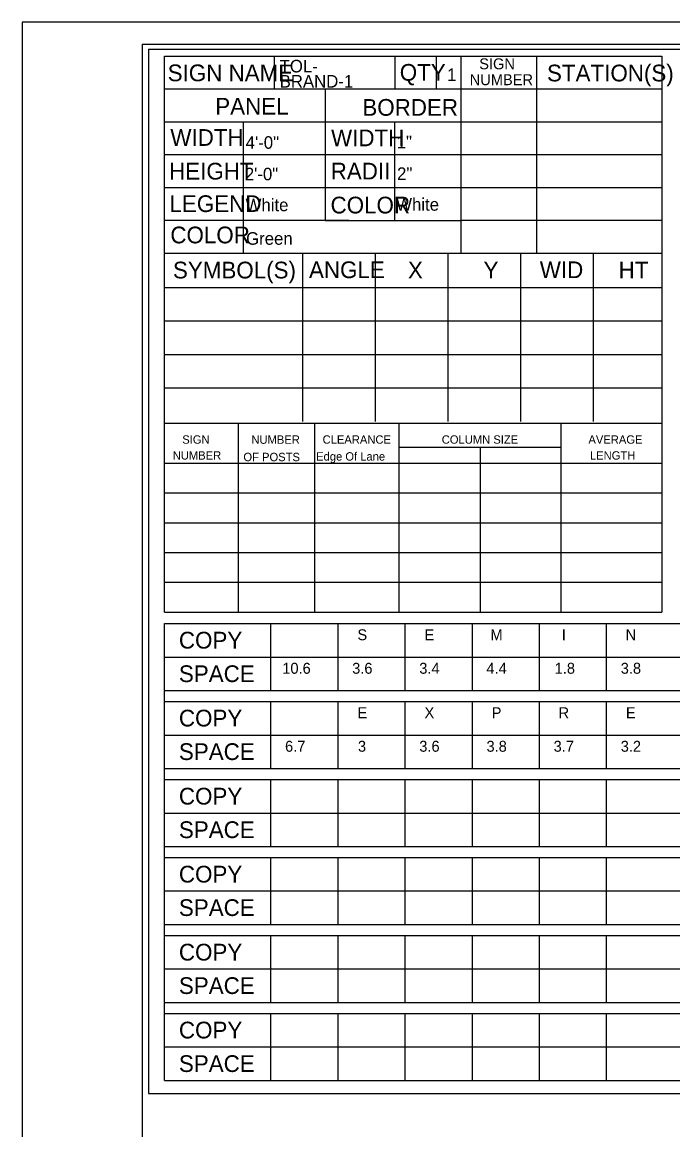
# Model space of a CAD drawing. Extents: x 17890587 to 17890754, y 17897693 to 17897992.
# Drawn here: x 17890586.76 to 17890595.51, y 17897889.3 to 17897904.2 of the extents above; entities that cross this region are included whole.
import ezdxf

# ---------------------------------------------------------------- set-up
doc = ezdxf.new("R2010")
doc.units = 0
for name, color, linetype in [('GSSign', 7, 'Continuous'), ('PlotBorder_dp', 7, 'Continuous'), ('SheetBorder_dp', 7, 'Continuous'), ('SheetLinesMisc2_dp', 7, 'Continuous'), ('TextMinor', 7, 'Continuous')]:
    doc.layers.add(name, color=color, linetype=linetype)

msp = doc.modelspace()

# ---------------------------------------------------------------- linework, layer by layer
at = {"layer": 'PlotBorder_dp'}
msp.add_lwpolyline([(17890586.756, 17897873.104), (17890635.165, 17897873.104), (17890635.165, 17897904.203), (17890586.756, 17897904.203)], close=True, dxfattribs=at)
at = {"layer": 'SheetBorder_dp'}
for q in [(17890588.37, 17897873.397), (17890633.551, 17897903.909)]:
    msp.add_line((17890588.37, 17897903.909), q, dxfattribs=at)
at = {"layer": 'SheetLinesMisc2_dp'}
for p, q in [((17890588.454, 17897903.839), (17890611.019, 17897903.839)), ((17890588.454, 17897903.839), (17890588.454, 17897889.792)), ((17890588.67, 17897896.269), (17890588.67, 17897903.746)), ((17890588.67, 17897903.746), (17890595.362, 17897903.746)), ((17890590.145, 17897903.746), (17890590.145, 17897903.304)), ((17890591.772, 17897903.746), (17890591.772, 17897903.304)), ((17890592.328, 17897903.746), (17890592.328, 17897903.304)), ((17890592.659, 17897903.746), (17890592.659, 17897901.096)), ((17890593.677, 17897903.746), (17890593.677, 17897901.096)), ((17890595.362, 17897903.746), (17890595.362, 17897896.269)), ((17890588.67, 17897903.304), (17890595.362, 17897903.304)), ((17890590.833, 17897903.304), (17890590.833, 17897901.533)), ((17890588.67, 17897902.862), (17890595.362, 17897902.862)), ((17890589.728, 17897902.862), (17890589.728, 17897901.096)), ((17890591.766, 17897902.858), (17890591.766, 17897901.533)), ((17890588.67, 17897902.421), (17890595.362, 17897902.421)), ((17890588.67, 17897901.979), (17890595.362, 17897901.979)), ((17890588.67, 17897901.538), (17890591.152, 17897901.538)), ((17890590.833, 17897901.533), (17890592.659, 17897901.533)), ((17890592.659, 17897901.538), (17890595.362, 17897901.538)), ((17890588.67, 17897901.096), (17890595.362, 17897901.096)), ((17890590.529, 17897901.087), (17890590.529, 17897898.832)), ((17890591.506, 17897901.087), (17890591.506, 17897898.832)), ((17890592.484, 17897901.087), (17890592.484, 17897898.832)), ((17890593.462, 17897901.087), (17890593.462, 17897898.832)), ((17890594.44, 17897901.087), (17890594.44, 17897898.832)), ((17890588.672, 17897900.636), (17890595.362, 17897900.636)), ((17890588.672, 17897900.185), (17890595.362, 17897900.185)), ((17890588.672, 17897899.734), (17890595.362, 17897899.734)), ((17890588.672, 17897899.283), (17890595.362, 17897899.283)), ((17890588.67, 17897898.811), (17890595.362, 17897898.811)), ((17890589.663, 17897898.811), (17890589.663, 17897896.269)), ((17890590.69, 17897898.811), (17890590.69, 17897896.269)), ((17890591.823, 17897898.811), (17890591.823, 17897896.269)), ((17890594.005, 17897898.811), (17890594.005, 17897896.269)), ((17890591.823, 17897898.488), (17890594.004, 17897898.488)), ((17890592.918, 17897898.488), (17890592.918, 17897896.269)), ((17890588.67, 17897898.272), (17890595.362, 17897898.272)), ((17890588.67, 17897897.871), (17890595.362, 17897897.871)), ((17890588.67, 17897897.471), (17890595.362, 17897897.471)), ((17890588.67, 17897897.07), (17890595.362, 17897897.07)), ((17890588.67, 17897896.67), (17890595.362, 17897896.67)), ((17890588.67, 17897896.269), (17890595.362, 17897896.269)), ((17890588.67, 17897896.115), (17890610.866, 17897896.115)), ((17890588.67, 17897889.969), (17890588.67, 17897896.115)), ((17890590.099, 17897896.115), (17890590.099, 17897895.213)), ((17890591.002, 17897896.115), (17890591.002, 17897895.213)), ((17890591.905, 17897896.115), (17890591.905, 17897895.213)), ((17890592.808, 17897896.115), (17890592.808, 17897895.213)), ((17890593.71, 17897896.115), (17890593.71, 17897895.213)), ((17890594.613, 17897896.115), (17890594.613, 17897895.213)), ((17890588.67, 17897895.664), (17890610.866, 17897895.664)), ((17890588.67, 17897895.213), (17890610.866, 17897895.213)), ((17890588.67, 17897895.066), (17890610.866, 17897895.066)), ((17890590.099, 17897895.066), (17890590.099, 17897894.164)), ((17890591.002, 17897895.066), (17890591.002, 17897894.164)), ((17890591.905, 17897895.066), (17890591.905, 17897894.164)), ((17890592.808, 17897895.066), (17890592.808, 17897894.164)), ((17890593.71, 17897895.066), (17890593.71, 17897894.164)), ((17890594.613, 17897895.066), (17890594.613, 17897894.164)), ((17890588.67, 17897894.615), (17890610.866, 17897894.615)), ((17890588.67, 17897894.164), (17890610.866, 17897894.164)), ((17890588.67, 17897894.017), (17890610.866, 17897894.017)), ((17890590.099, 17897894.017), (17890590.099, 17897893.116)), ((17890591.002, 17897894.017), (17890591.002, 17897893.116)), ((17890591.905, 17897894.017), (17890591.905, 17897893.116)), ((17890592.808, 17897894.017), (17890592.808, 17897893.116)), ((17890593.71, 17897894.017), (17890593.71, 17897893.116)), ((17890594.613, 17897894.017), (17890594.613, 17897893.116)), ((17890588.67, 17897893.566), (17890610.866, 17897893.566)), ((17890588.67, 17897893.116), (17890610.866, 17897893.116)), ((17890588.67, 17897892.969), (17890610.866, 17897892.969)), ((17890590.099, 17897892.969), (17890590.099, 17897892.067)), ((17890591.002, 17897892.969), (17890591.002, 17897892.067)), ((17890591.905, 17897892.969), (17890591.905, 17897892.067)), ((17890592.808, 17897892.969), (17890592.808, 17897892.067)), ((17890593.71, 17897892.969), (17890593.71, 17897892.067)), ((17890594.613, 17897892.969), (17890594.613, 17897892.067)), ((17890588.67, 17897892.518), (17890610.866, 17897892.518)), ((17890588.67, 17897892.067), (17890610.866, 17897892.067)), ((17890588.67, 17897891.92), (17890610.866, 17897891.92)), ((17890590.099, 17897891.92), (17890590.099, 17897891.018)), ((17890591.002, 17897891.92), (17890591.002, 17897891.018)), ((17890591.905, 17897891.92), (17890591.905, 17897891.018)), ((17890592.808, 17897891.92), (17890592.808, 17897891.018)), ((17890593.71, 17897891.92), (17890593.71, 17897891.018)), ((17890594.613, 17897891.92), (17890594.613, 17897891.018)), ((17890588.67, 17897891.469), (17890610.866, 17897891.469)), ((17890588.67, 17897891.018), (17890610.866, 17897891.018)), ((17890588.67, 17897890.871), (17890610.866, 17897890.871)), ((17890590.099, 17897890.871), (17890590.099, 17897889.969)), ((17890591.002, 17897890.871), (17890591.002, 17897889.969)), ((17890591.905, 17897890.871), (17890591.905, 17897889.969)), ((17890592.808, 17897890.871), (17890592.808, 17897889.969)), ((17890593.71, 17897890.871), (17890593.71, 17897889.969)), ((17890594.613, 17897890.871), (17890594.613, 17897889.969)), ((17890588.67, 17897890.42), (17890610.866, 17897890.42)), ((17890588.67, 17897889.969), (17890610.866, 17897889.969)), ((17890588.454, 17897889.792), (17890611.019, 17897889.792))]:
    msp.add_line(p, q, dxfattribs=at)

# ---------------------------------------------------------------- texts
at = {"layer": 'GSSign'}
for s, height, p in [('TOL-', 0.1687, (17890590.22, 17897903.527)), ('1', 0.169, (17890592.472, 17897903.412)), ('BRAND-1', 0.1687, (17890590.22, 17897903.323)), ('4\'-0"', 0.1687, (17890589.763, 17897902.5)), ('1"', 0.1687, (17890591.795, 17897902.506)), ('2\'-0"', 0.1687, (17890589.752, 17897902.076)), ('2"', 0.1687, (17890591.8, 17897902.081)), ('White', 0.1687, (17890589.762, 17897901.66)), ('White', 0.1687, (17890591.788, 17897901.667)), ('Green', 0.1687, (17890589.769, 17897901.209)), ('S', 0.147, (17890591.267, 17897895.89)), ('E', 0.147, (17890592.17, 17897895.89)), ('M', 0.147, (17890593.056, 17897895.89)), ('I', 0.147, (17890594.016, 17897895.89)), ('N', 0.147, (17890594.873, 17897895.89)), ('10.6', 0.147, (17890590.256, 17897895.439)), ('3.6', 0.147, (17890591.196, 17897895.439)), ('3.4', 0.147, (17890592.099, 17897895.439)), ('4.4', 0.147, (17890593.002, 17897895.439)), ('1.8', 0.147, (17890593.92, 17897895.439)), ('3.8', 0.147, (17890594.809, 17897895.439)), ('E', 0.147, (17890591.267, 17897894.841)), ('X', 0.147, (17890592.169, 17897894.841)), ('P', 0.147, (17890593.073, 17897894.841)), ('R', 0.147, (17890593.972, 17897894.841)), ('E', 0.147, (17890594.879, 17897894.841)), ('6.7', 0.147, (17890590.293, 17897894.39)), ('3', 0.147, (17890591.274, 17897894.39)), ('3.6', 0.147, (17890592.099, 17897894.39)), ('3.8', 0.147, (17890593.003, 17897894.39)), ('3.7', 0.147, (17890593.906, 17897894.39)), ('3.2', 0.147, (17890594.809, 17897894.39))]:
    msp.add_text(s, height=height, dxfattribs=at).set_placement(p)
at = {"layer": 'TextMinor'}
for s, height, p in [('SIGN', 0.147, (17890592.905, 17897903.569)), ('SIGN NAME', 0.225, (17890588.714, 17897903.408)), ('QTY', 0.225, (17890591.836, 17897903.415)), ('STATION(S)', 0.225, (17890593.817, 17897903.406)), ('NUMBER', 0.147, (17890592.777, 17897903.355)), ('PANEL', 0.225, (17890589.354, 17897902.959)), ('BORDER', 0.225, (17890591.333, 17897902.944)), ('WIDTH', 0.225, (17890588.75, 17897902.539)), ('WIDTH', 0.225, (17890590.912, 17897902.534)), ('HEIGHT', 0.225, (17890588.733, 17897902.086)), ('RADII', 0.225, (17890590.907, 17897902.087)), ('LEGEND', 0.225, (17890588.738, 17897901.649)), ('COLOR', 0.225, (17890590.905, 17897901.63)), ('COLOR', 0.225, (17890588.75, 17897901.228)), ('SYMBOL(S)', 0.225, (17890588.785, 17897900.756)), ('ANGLE', 0.225, (17890590.615, 17897900.76)), ('X', 0.225, (17890591.946, 17897900.756)), ('Y', 0.225, (17890592.963, 17897900.756)), ('WID', 0.225, (17890593.72, 17897900.76)), ('HT', 0.225, (17890594.78, 17897900.756)), ('SIGN', 0.1125, (17890588.91, 17897898.533)), ('NUMBER', 0.1125, (17890589.84, 17897898.532)), ('CLEARANCE', 0.1125, (17890590.798, 17897898.533)), ('COLUMN SIZE', 0.11249, (17890592.401, 17897898.533)), ('AVERAGE', 0.1125, (17890594.374, 17897898.533)), ('NUMBER', 0.1125, (17890588.782, 17897898.319)), ('OF POSTS', 0.1125, (17890589.733, 17897898.298)), ('Edge Of Lane', 0.11249, (17890590.711, 17897898.306)), ('LENGTH', 0.1125, (17890594.395, 17897898.319)), ('COPY', 0.225, (17890588.865, 17897895.778)), ('SPACE', 0.225, (17890588.865, 17897895.327)), ('COPY', 0.225, (17890588.865, 17897894.73)), ('SPACE', 0.225, (17890588.865, 17897894.279)), ('COPY', 0.225, (17890588.865, 17897893.68)), ('SPACE', 0.225, (17890588.865, 17897893.229)), ('COPY', 0.225, (17890588.865, 17897892.631)), ('SPACE', 0.225, (17890588.865, 17897892.181)), ('COPY', 0.225, (17890588.865, 17897891.582)), ('SPACE', 0.225, (17890588.865, 17897891.132)), ('COPY', 0.225, (17890588.865, 17897890.534)), ('SPACE', 0.225, (17890588.865, 17897890.083))]:
    msp.add_text(s, height=height, dxfattribs=at).set_placement(p)

doc.saveas('drawing.dxf')
